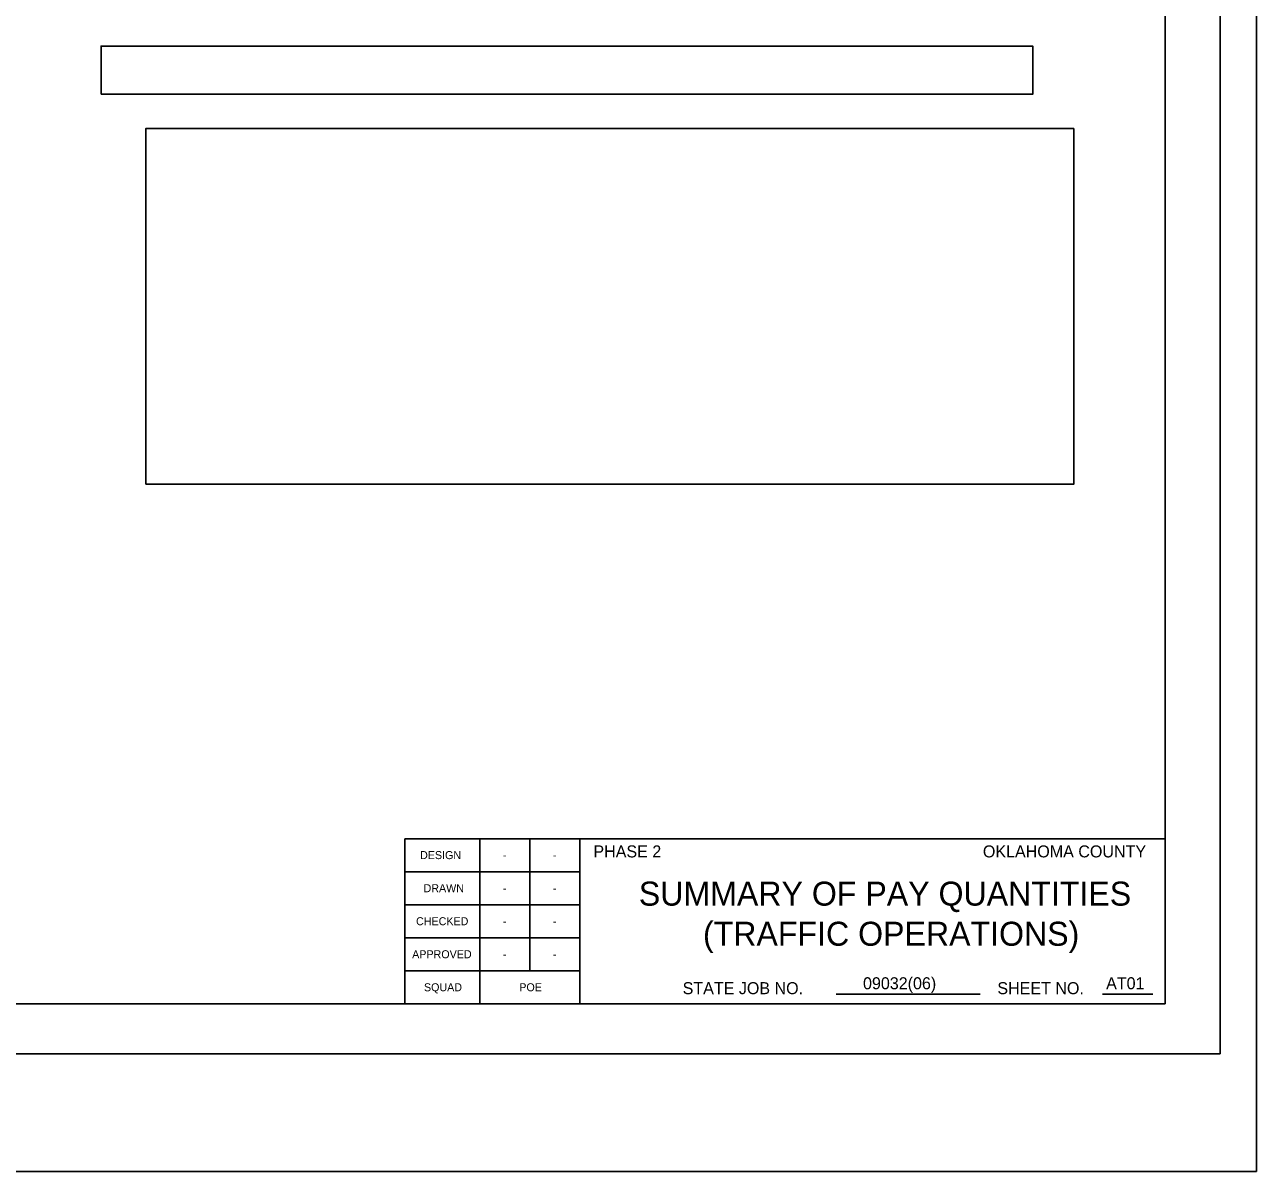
# Model space of a CAD drawing. Extents: x -98.3 to -54.8, y -26.7 to 2.7.
# Drawn here: x -74.57 to -62.26, y -26.7 to -15.24 of the extents above; entities that cross this region are included whole.
import ezdxf

# ---------------------------------------------------------------- set-up
doc = ezdxf.new("R2010")
doc.units = 0
for name, color, linetype in [('SHT_Plot_Shape_Full', 7, 'Continuous'), ('SHT_Plot_Shape_Half', 7, 'Continuous'), ('SHT_Sheet_Border', 7, 'Continuous'), ('SHT_Sheet_Txt', 7, 'Continuous'), ('SHT_Standard_Sheet_Lines', 7, 'Continuous'), ('SHT_Standard_Sheet_Txt', 7, 'Continuous')]:
    doc.layers.add(name, color=color, linetype=linetype)

msp = doc.modelspace()

# ---------------------------------------------------------------- linework, layer by layer
at = {"layer": 'SHT_Plot_Shape_Full'}
msp.add_lwpolyline([(-98.262, -2.701), (-62.262, -2.701), (-62.262, -26.701), (-98.262, -26.701)], close=True, dxfattribs=at)
at = {"layer": 'SHT_Plot_Shape_Half'}
msp.add_lwpolyline([(-96.625, -3.526), (-62.625, -3.526), (-62.625, -25.526), (-96.625, -25.526)], close=True, dxfattribs=at)
at = {"layer": 'SHT_Sheet_Border'}
for p, q in [((-70.775, -25.026), (-70.775, -23.376)), ((-70.775, -23.376), (-63.175, -23.376)), ((-69.025, -25.026), (-69.025, -23.375))]:
    msp.add_line(p, q, dxfattribs=at)
msp.add_lwpolyline([(-94.675, -25.026), (-63.175, -25.026), (-63.175, -4.026), (-94.675, -4.026)], close=True, dxfattribs=at)
at = {"layer": 'SHT_Sheet_Txt'}
for points in [[(-73.811, -15.935), (-64.497, -15.935), (-64.497, -15.453), (-73.811, -15.453)], [(-73.364, -19.833), (-64.087, -19.833), (-64.087, -16.278), (-73.364, -16.278)]]:
    msp.add_lwpolyline(points, close=True, dxfattribs=at)
at = {"layer": 'SHT_Standard_Sheet_Lines'}
for p, q in [((-70.025, -25.026), (-70.025, -23.375)), ((-69.525, -24.696), (-69.525, -23.375)), ((-66.464, -24.93), (-65.024, -24.93)), ((-63.799, -24.93), (-63.297, -24.93))]:
    msp.add_line(p, q, dxfattribs=at)
for points in [[(-69.025, -23.706), (-70.775, -23.706)], [(-69.025, -24.036), (-70.775, -24.036)], [(-69.025, -24.366), (-70.775, -24.366)], [(-69.025, -24.696), (-70.775, -24.696)]]:
    msp.add_lwpolyline(points, dxfattribs=at)

# ---------------------------------------------------------------- texts
at = {"layer": 'SHT_Standard_Sheet_Txt'}
for s, height, p in [('DESIGN', 0.08, (-70.622, -23.58)), ('-', 0.08, (-69.794, -23.58)), ('-', 0.08, (-69.294, -23.58)), ('DRAWN', 0.08, (-70.587, -23.911)), ('-', 0.08, (-69.794, -23.911)), ('-', 0.08, (-69.294, -23.911)), ('SUMMARY OF PAY QUANTITIES', 0.24, (-68.435, -24.045)), ('CHECKED', 0.08, (-70.662, -24.241)), ('-', 0.08, (-69.794, -24.241)), ('-', 0.08, (-69.294, -24.241)), ('(TRAFFIC OPERATIONS)', 0.24, (-67.794, -24.446)), ('APPROVED', 0.08, (-70.701, -24.571)), ('-', 0.08, (-69.794, -24.571)), ('-', 0.08, (-69.294, -24.571)), ('SQUAD', 0.08, (-70.583, -24.901)), ('POE', 0.08, (-69.63, -24.901)), ('STATE JOB NO.', 0.12, (-67.997, -24.93)), ('09032(06)', 0.12, (-66.194, -24.881)), ('SHEET NO. ', 0.12, (-64.851, -24.93)), ('AT01', 0.12, (-63.764, -24.881))]:
    msp.add_text(s, height=height, dxfattribs=at).set_placement(p)
for s, p in [('PHASE 2', (-68.889, -23.563)), ('OKLAHOMA COUNTY', (-64.996, -23.563))]:
    msp.add_text(s, height=0.12, rotation=360, dxfattribs=at).set_placement(p)

doc.saveas('drawing.dxf')
